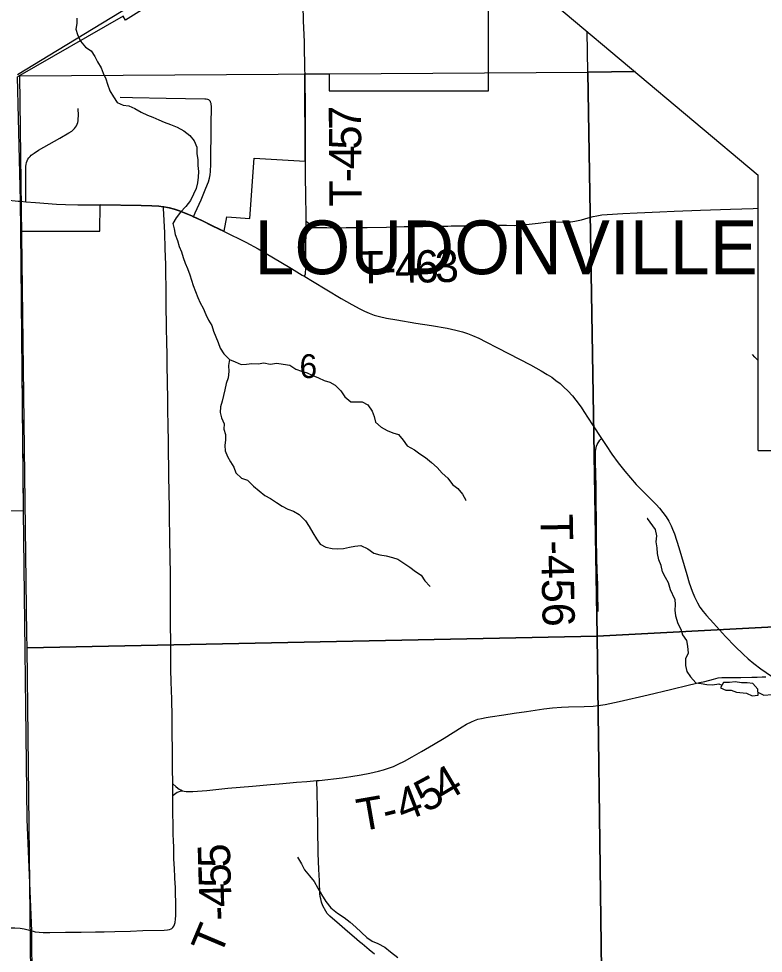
# Model space of a CAD drawing. Extents: x 0 to 34, y 0 to 22.
# Drawn here: x 4.117 to 5.429, y 15.182 to 16.828 of the extents above; entities that cross this region are included whole.
import ezdxf

# ---------------------------------------------------------------- set-up
doc = ezdxf.new("R2010")
doc.units = 0
for name, color, linetype in [('GM_X_City_Street', 7, 'Continuous'), ('GM_X_County_Road', 7, 'Continuous'), ('GM_X_County_Road_Text', 7, 'Continuous'), ('GM_X_County_Text', 7, 'Continuous'), ('GM_X_Interchange_Ramps', 7, 'Continuous'), ('GM_X_Minor_River_Text', 7, 'Continuous'), ('GM_X_State_Location', 7, 'Continuous'), ('GM_X_State_Route', 7, 'Continuous'), ('GM_X_Township_Text', 7, 'Continuous'), ('SH_Text', 7, 'Continuous')]:
    doc.layers.add(name, color=color, linetype=linetype)

msp = doc.modelspace()

# ---------------------------------------------------------------- linework, layer by layer
at = {"layer": 'GM_X_County_Road'}
msp.add_line((4.1203, 16.5064), (4.1296, 16.5056), dxfattribs=at)
for points in [[(4.0462, 16.5135), (4.0536, 16.5129), (4.0752, 16.5107), (4.0939, 16.5088), (4.1156, 16.5068), (4.1203, 16.5064)], [(4.1296, 16.5056), (4.1462, 16.5042), (4.1835, 16.5016), (4.1991, 16.501), (4.2212, 16.5004), (4.2606, 16.5), (4.3328, 16.4993), (4.3514, 16.4986), (4.3638, 16.4977), (4.3717, 16.4967)], [(4.3717, 16.4967), (4.373, 16.4965), (4.3821, 16.4948), (4.391, 16.4926), (4.3998, 16.4896), (4.4113, 16.4852), (4.4228, 16.4805), (4.425, 16.4793)], [(4.425, 16.4793), (4.4393, 16.4724), (4.459, 16.4629), (4.4789, 16.4531)], [(4.4789, 16.4531), (4.517, 16.4344), (4.5388, 16.4226), (4.563, 16.4086), (4.5975, 16.3879), (4.6162, 16.3765), (4.6208, 16.3738)], [(4.6208, 16.3738), (4.6346, 16.3655), (4.6853, 16.3352), (4.7036, 16.3244), (4.7177, 16.3168), (4.7261, 16.3128), (4.7344, 16.3091), (4.7433, 16.306), (4.7525, 16.3036), (4.7647, 16.3008), (4.783, 16.2976), (4.8167, 16.2918), (4.8441, 16.2875), (4.8717, 16.2828), (4.8868, 16.2796), (4.8987, 16.2765), (4.9075, 16.2736), (4.9162, 16.2703), (4.9275, 16.2652), (4.9402, 16.259), (4.9607, 16.2484), (5.0186, 16.2183), (5.0377, 16.2079), (5.0483, 16.2016), (5.0561, 16.1965), (5.0635, 16.191), (5.0707, 16.1852), (5.0776, 16.179), (5.0842, 16.1725), (5.0927, 16.1635), (5.0985, 16.1563), (5.1077, 16.1439), (5.1129, 16.1361), (5.128, 16.1125), (5.1435, 16.0887)], [(5.1435, 16.0887), (5.1517, 16.0761), (5.1621, 16.0607), (5.1731, 16.0457), (5.1846, 16.031), (5.1946, 16.0192), (5.2051, 16.0077), (5.2225, 15.99), (5.24, 15.9724), (5.2462, 15.9656), (5.2521, 15.9584), (5.2574, 15.9508), (5.2622, 15.9429), (5.2665, 15.9347), (5.269, 15.9291), (5.2722, 15.9204), (5.2803, 15.8964), (5.294, 15.8492), (5.2985, 15.8345), (5.3034, 15.8199), (5.3074, 15.8098), (5.3128, 15.7993), (5.3172, 15.7916), (5.3227, 15.7839), (5.3287, 15.7768), (5.3409, 15.763), (5.3623, 15.7397), (5.3792, 15.7219), (5.3931, 15.7088), (5.4023, 15.7004), (5.4119, 15.6924), (5.4243, 15.6831), (5.4432, 15.6697)]]:
    msp.add_lwpolyline(points, dxfattribs=at)
at = {"layer": 'GM_X_County_Road_Text'}
for points in [[(4.2192, 16.8292), (4.2191, 16.8197), (4.2175, 16.8095), (4.2204, 16.8), (4.226, 16.7886), (4.2347, 16.7782), (4.2448, 16.7717), (4.2512, 16.7618), (4.2557, 16.7523), (4.262, 16.7416), (4.2657, 16.7321), (4.2702, 16.7222), (4.2732, 16.7127), (4.2772, 16.7013), (4.284, 16.6902), (4.2903, 16.6807), (4.3009, 16.6756), (4.3111, 16.6744), (4.3217, 16.6698), (4.3326, 16.6636), (4.3436, 16.6582), (4.3534, 16.6547), (4.3636, 16.65), (4.3734, 16.6458), (4.3844, 16.6415), (4.3961, 16.6369), (4.4078, 16.6307), (4.4183, 16.6226), (4.4258, 16.6131), (4.4307, 16.602), (4.431, 16.5899), (4.4324, 16.58), (4.4327, 16.5694), (4.4334, 16.5592), (4.4329, 16.5489), (4.4321, 16.5387), (4.4297, 16.5289), (4.4251, 16.519), (4.4197, 16.5081), (4.4112, 16.4972), (4.4017, 16.4874), (4.3944, 16.4772), (4.3886, 16.4674), (4.3905, 16.4579), (4.3926, 16.448), (4.3967, 16.4374), (4.3997, 16.4271), (4.4038, 16.4176), (4.4067, 16.4073), (4.4104, 16.3974), (4.4141, 16.3879), (4.4186, 16.3769), (4.4212, 16.3674), (4.4241, 16.3579), (4.4282, 16.3476), (4.4323, 16.337), (4.4364, 16.3274), (4.4416, 16.3179), (4.4464, 16.3069), (4.4513, 16.297), (4.4573, 16.2874), (4.4598, 16.2775), (4.4639, 16.2676), (4.4684, 16.2577), (4.4721, 16.2479), (4.4785, 16.2376), (4.4882, 16.2276), (4.4981, 16.2237), (4.5086, 16.2191), (4.5181, 16.2194), (4.5276, 16.2208), (4.5386, 16.22), (4.5488, 16.2221), (4.5598, 16.2198), (4.5716, 16.2212), (4.5829, 16.2195), (4.5947, 16.2175), (4.6052, 16.2106), (4.6154, 16.2071), (4.6252, 16.204), (4.6351, 16.1994), (4.6449, 16.1955), (4.6551, 16.1908), (4.6649, 16.1877), (4.6747, 16.1823), (4.6845, 16.1724)], [(5.4199, 16.2257), (5.4142, 16.2321), (5.4101, 16.2363)], [(4.4882, 16.2276), (4.4866, 16.217), (4.4873, 16.2068), (4.4857, 16.1954), (4.4826, 16.1856), (4.4802, 16.1742), (4.4755, 16.1545), (4.4724, 16.1443), (4.4719, 16.1345), (4.4741, 16.125), (4.4786, 16.1147), (4.4785, 16.1052), (4.4811, 16.0957), (4.481, 16.0862), (4.4802, 16.0764), (4.4805, 16.0669), (4.4845, 16.057), (4.4902, 16.0475), (4.4961, 16.0379), (4.4995, 16.028), (4.5096, 16.0188), (4.5198, 16.015), (4.5307, 16.0046), (4.5405, 15.9962), (4.5507, 15.9881), (4.5605, 15.9831), (4.5711, 15.9758), (4.5809, 15.9693), (4.591, 15.9639), (4.6009, 15.9604), (4.6111, 15.955), (4.622, 15.9435), (4.6287, 15.9336), (4.635, 15.9222), (4.6418, 15.9119), (4.6478, 15.9023), (4.658, 15.8969), (4.6689, 15.8949), (4.6788, 15.8945), (4.689, 15.8951), (4.6996, 15.8969), (4.7091, 15.8987), (4.7198, 15.9002), (4.7318, 15.894), (4.7428, 15.8867), (4.7534, 15.8835), (4.7643, 15.8819), (4.7753, 15.8788), (4.7851, 15.876), (4.7953, 15.8688), (4.8059, 15.8622), (4.816, 15.8542), (4.8258, 15.848), (4.8322, 15.8381), (4.8412, 15.8285), (4.842, 15.8281)], [(4.6845, 16.1724), (4.6912, 16.1621), (4.7021, 16.1532), (4.7222, 16.1531), (4.732, 16.1477), (4.7399, 16.1366), (4.7429, 16.1271), (4.7454, 16.1172), (4.7556, 16.1088), (4.7658, 16.1026), (4.776, 16.0987), (4.7858, 16.0956), (4.7944, 16.0857), (4.8016, 16.0757), (4.814, 16.0688), (4.8238, 16.0615), (4.8336, 16.055), (4.8442, 16.0465), (4.8539, 16.0374), (4.863, 16.0278), (4.8727, 16.0186), (4.881, 16.0075), (4.8908, 16.0006), (4.8987, 15.9903), (4.9046, 15.98), (4.9042, 15.9796)], [(5.273, 15.8056), (5.2653, 15.822), (5.2616, 15.8342), (5.2568, 15.8437), (5.2515, 15.8536), (5.2486, 15.865), (5.2449, 15.8749), (5.2423, 15.8859), (5.2416, 15.8958), (5.2402, 15.9064), (5.2414, 15.9174), (5.2389, 15.9284), (5.2246, 15.9475), (5.2243, 15.9479)], [(5.273, 15.8056), (5.2735, 15.7958), (5.2728, 15.7859), (5.2744, 15.7761), (5.2783, 15.7628), (5.2833, 15.753), (5.2865, 15.7428), (5.2934, 15.733), (5.295, 15.7227), (5.2966, 15.7106), (5.2918, 15.7007), (5.2919, 15.689), (5.2942, 15.6784), (5.3004, 15.6685), (5.31, 15.658), (5.3194, 15.6569), (5.3293, 15.6555), (5.3395, 15.6545), (5.3505, 15.6564), (5.3559, 15.6538)], [(5.4194, 15.6418), (5.4295, 15.6362), (5.4447, 15.6375)], [(4.608, 15.3513), (4.6153, 15.3396), (4.6207, 15.329), (4.6291, 15.3181), (4.6375, 15.3083), (4.6437, 15.2966), (4.6506, 15.2852), (4.6579, 15.2728), (4.6668, 15.2619), (4.6786, 15.2525), (4.6904, 15.245), (4.7007, 15.2367), (4.711, 15.2277), (4.7301, 15.2097), (4.7397, 15.2033), (4.7499, 15.1992), (4.7621, 15.1925), (4.772, 15.1846), (4.785, 15.1741)]]:
    msp.add_lwpolyline(points, dxfattribs=at)
at = {"layer": 'GM_X_County_Text'}
msp.add_lwpolyline([(4.1146, 16.7296), (4.185, 16.7727), (4.3934, 16.8994)], dxfattribs=at)
at = {"layer": 'GM_X_Interchange_Ramps'}
for points in [[(4.6214, 16.732), (4.6214, 16.733), (4.6213, 16.7361), (4.6212, 16.741), (4.6211, 16.7443), (4.621, 16.7494), (4.6209, 16.7541), (4.621, 16.7567), (4.621, 16.7599), (4.6207, 16.7628), (4.6206, 16.7658), (4.6205, 16.7719), (4.6202, 16.7874), (4.6189, 16.8245), (4.6172, 16.8799), (4.6156, 16.9322), (4.6153, 16.9575), (4.6153, 16.9681), (4.6153, 16.9872), (4.6153, 16.9997), (4.6151, 17.0071), (4.6145, 17.0131), (4.6135, 17.018)], [(4.6219, 16.5766), (4.6219, 16.5966), (4.6219, 16.6039), (4.622, 16.6136), (4.6221, 16.6218), (4.6221, 16.631), (4.6222, 16.6446), (4.6223, 16.6553), (4.6223, 16.6618), (4.6224, 16.6676), (4.6223, 16.6738), (4.6221, 16.6845), (4.6219, 16.6936), (4.6218, 16.7018), (4.6217, 16.7105), (4.6216, 16.7171), (4.6216, 16.7207), (4.6215, 16.7265), (4.6214, 16.731), (4.6214, 16.732)], [(4.6236, 16.4712), (4.6236, 16.4721), (4.6235, 16.4812), (4.6234, 16.4904), (4.623, 16.5081), (4.6226, 16.5241), (4.6221, 16.5425), (4.6221, 16.5484), (4.622, 16.5579), (4.6219, 16.5766)], [(4.384, 15.8716), (4.3839, 15.8798), (4.3833, 15.9109), (4.3825, 15.9544), (4.3823, 15.973), (4.3821, 15.9864), (4.3819, 16), (4.3816, 16.0168), (4.3813, 16.0351), (4.3808, 16.0662), (4.3805, 16.0817), (4.3801, 16.1125), (4.3798, 16.1373), (4.3797, 16.159), (4.3793, 16.1869), (4.3787, 16.219), (4.3784, 16.2366), (4.3781, 16.2584), (4.3775, 16.2832), (4.3773, 16.2925), (4.3768, 16.3173), (4.3764, 16.3329), (4.3766, 16.3577), (4.3763, 16.3764), (4.376, 16.395), (4.3751, 16.4229), (4.3742, 16.4509), (4.3732, 16.4726), (4.3719, 16.4941), (4.3717, 16.4967)], [(4.8092, 16.462), (4.8292, 16.4623), (4.8611, 16.4625), (4.8672, 16.4627), (4.8732, 16.4629), (4.8789, 16.4632), (4.8918, 16.4633), (4.9125, 16.4634), (4.927, 16.4637), (4.9504, 16.4641), (4.9621, 16.4642), (4.9761, 16.4641), (4.9906, 16.464), (5.0007, 16.4647), (5.0102, 16.4657), (5.0164, 16.4663), (5.032, 16.4681), (5.0456, 16.4695), (5.0613, 16.4703), (5.0775, 16.4697), (5.0842, 16.4701), (5.0899, 16.4704), (5.0967, 16.4717), (5.1027, 16.4727), (5.1084, 16.4739), (5.1203, 16.4772), (5.1293, 16.4797), (5.1353, 16.4811), (5.1445, 16.4826), (5.1538, 16.4834), (5.1816, 16.4848), (5.2065, 16.4859), (5.2468, 16.4877), (5.2716, 16.4889), (5.3181, 16.4907), (5.3709, 16.4925), (5.4112, 16.494), (5.4199, 16.4946)], [(4.6234, 16.4558), (4.6235, 16.4614), (4.6236, 16.4712)], [(4.6236, 16.4712), (4.6295, 16.4665), (4.633, 16.4637), (4.6373, 16.4603)], [(4.6208, 16.3738), (4.6213, 16.3757), (4.6219, 16.3785), (4.6223, 16.3816), (4.6226, 16.3864), (4.6227, 16.3895), (4.6226, 16.3957), (4.6227, 16.4112), (4.6227, 16.4159), (4.6227, 16.4214), (4.6227, 16.4261), (4.6229, 16.4336), (4.6232, 16.4454), (4.6234, 16.4513), (4.6234, 16.4558)], [(4.6234, 16.4558), (4.6277, 16.4577), (4.6313, 16.459), (4.6336, 16.4597), (4.6349, 16.46), (4.6363, 16.4601), (4.6373, 16.4603)], [(4.6373, 16.4603), (4.6379, 16.4603), (4.6441, 16.4604), (4.6596, 16.46), (4.6752, 16.4599), (4.6938, 16.46), (4.7167, 16.4603), (4.7311, 16.4605), (4.7652, 16.4609), (4.7963, 16.4618), (4.8092, 16.462)], [(5.1381, 15.7837), (5.1381, 15.7899), (5.1375, 15.8117), (5.1373, 15.821), (5.1372, 15.8303), (5.1371, 15.8334), (5.1369, 15.8427), (5.1363, 15.8581), (5.136, 15.8642), (5.1357, 15.8704), (5.1354, 15.8828), (5.1352, 15.9076), (5.1349, 15.9356), (5.1343, 15.9853), (5.1341, 16.004), (5.1339, 16.0258), (5.1337, 16.032), (5.1334, 16.0413), (5.1332, 16.0506), (5.1331, 16.0599), (5.1332, 16.0661), (5.1336, 16.0692), (5.1342, 16.0723), (5.135, 16.0753), (5.1362, 16.0781), (5.1377, 16.0808), (5.139, 16.0826), (5.1411, 16.0855), (5.1435, 16.0887)], [(4.3874, 15.5639), (4.387, 15.5981), (4.3866, 15.6292), (4.3856, 15.6602), (4.3851, 15.6819), (4.3847, 15.7037), (4.3847, 15.7099), (4.3847, 15.7266), (4.3847, 15.7395), (4.3846, 15.7517), (4.3846, 15.7649), (4.3845, 15.7782), (4.3844, 15.7925), (4.3843, 15.8116), (4.3842, 15.8364), (4.3841, 15.8581), (4.384, 15.8716)], [(4.642, 15.486), (4.6464, 15.4864), (4.6865, 15.4909), (4.7019, 15.4932), (4.7203, 15.4962), (4.7355, 15.4991), (4.7506, 15.5024), (4.7596, 15.5048), (4.7685, 15.5076), (4.7772, 15.5109), (4.7857, 15.5147), (4.7968, 15.5203), (4.8104, 15.5278), (4.8266, 15.537), (4.848, 15.5496), (4.8666, 15.5609), (4.898, 15.5808), (4.9061, 15.5855), (4.9145, 15.5897), (4.9202, 15.5921), (4.9261, 15.594), (4.9321, 15.5956), (4.9404, 15.5972), (4.9473, 15.5983), (4.9717, 15.6021), (4.9901, 15.6047), (5.0116, 15.6077), (5.0422, 15.6122), (5.0576, 15.614), (5.0731, 15.6153), (5.0854, 15.6158), (5.1134, 15.6164), (5.1289, 15.6173), (5.1381, 15.6182), (5.1504, 15.6201), (5.1747, 15.6251), (5.2261, 15.6372), (5.2654, 15.6463), (5.2986, 15.6544), (5.3167, 15.6589), (5.3257, 15.6608), (5.3413, 15.6648), (5.3495, 15.667), (5.3559, 15.6677), (5.3634, 15.6677), (5.3736, 15.6675), (5.3893, 15.6675), (5.4087, 15.6679), (5.418, 15.6683), (5.4271, 15.6685), (5.4332, 15.6688)], [(4.3884, 15.4801), (4.3882, 15.4865), (4.388, 15.5024), (4.3877, 15.5205), (4.3877, 15.536), (4.3876, 15.5484), (4.3875, 15.5608), (4.3874, 15.5639)], [(4.3884, 15.4801), (4.3939, 15.4755), (4.3972, 15.4728), (4.3997, 15.4711), (4.4025, 15.4696), (4.4056, 15.4682)], [(4.3884, 15.4595), (4.3884, 15.4671), (4.3885, 15.4772), (4.3884, 15.4801)], [(4.4056, 15.4682), (4.4085, 15.4674), (4.4121, 15.4669), (4.4176, 15.4666), (4.4238, 15.4667), (4.4486, 15.4687), (4.464, 15.4703), (4.4856, 15.4724), (4.5072, 15.4743), (4.5288, 15.4763), (4.5603, 15.4792), (4.576, 15.4805), (4.5943, 15.482), (4.6062, 15.483), (4.6248, 15.4843), (4.642, 15.486)], [(4.7437, 15.1804), (4.7343, 15.1878), (4.7218, 15.1985), (4.7171, 15.2021), (4.7077, 15.2101), (4.696, 15.2204), (4.6822, 15.2322), (4.6649, 15.2469), (4.6604, 15.252), (4.6578, 15.256), (4.6528, 15.2655), (4.6506, 15.2717), (4.6495, 15.2747), (4.649, 15.2774), (4.6481, 15.2817), (4.6477, 15.2868), (4.6473, 15.2961), (4.647, 15.2992), (4.6466, 15.3097), (4.6461, 15.3195), (4.6456, 15.3299), (4.6447, 15.3578), (4.644, 15.4013), (4.6433, 15.4417), (4.643, 15.4603), (4.6425, 15.4727), (4.6422, 15.479), (4.642, 15.486)], [(4.3884, 15.4595), (4.3911, 15.462), (4.3935, 15.4639), (4.396, 15.4654), (4.3983, 15.4664), (4.4015, 15.4674), (4.4056, 15.4682)], [(4.3891, 15.4033), (4.3889, 15.4122), (4.3887, 15.425), (4.3885, 15.4325), (4.3884, 15.4424), (4.3884, 15.4503), (4.3884, 15.4595)], [(4.1402, 15.2211), (4.1421, 15.2205), (4.1459, 15.2198), (4.1527, 15.2191), (4.16, 15.2186), (4.1719, 15.2185), (4.1992, 15.2187), (4.2271, 15.2191), (4.2519, 15.2194), (4.2674, 15.2196), (4.286, 15.2201), (4.314, 15.221), (4.3357, 15.2218), (4.373, 15.2227), (4.3792, 15.2232), (4.3824, 15.2238), (4.3855, 15.2249), (4.3868, 15.2257), (4.3882, 15.2269), (4.3902, 15.2296), (4.3916, 15.2326), (4.3924, 15.2357), (4.3934, 15.2419), (4.3938, 15.2482), (4.3938, 15.2606), (4.393, 15.2978), (4.3922, 15.3133), (4.3919, 15.3164), (4.3912, 15.3308), (4.3904, 15.348), (4.3901, 15.3581), (4.3899, 15.3679), (4.3896, 15.3804), (4.3893, 15.3908), (4.3891, 15.3993), (4.3891, 15.4033)], [(3.882, 15.2231), (3.8894, 15.2232), (3.9019, 15.2234), (3.9174, 15.2236), (3.936, 15.2238), (3.9547, 15.2239), (3.9733, 15.2241), (3.9982, 15.2243), (4.02, 15.2246), (4.0449, 15.2252), (4.0604, 15.2255), (4.0822, 15.2263), (4.1009, 15.2268), (4.1102, 15.2267), (4.1195, 15.2259), (4.1266, 15.2248), (4.1333, 15.2232), (4.1402, 15.2211)]]:
    msp.add_lwpolyline(points, dxfattribs=at)
at = {"layer": 'GM_X_Minor_River_Text'}
for points in [[(5.4104, 15.6569), (5.4005, 15.658), (5.3907, 15.6583), (5.3793, 15.6597), (5.3691, 15.6589), (5.3588, 15.6588), (5.3532, 15.6493), (5.3627, 15.6455), (5.3722, 15.6452), (5.3817, 15.6419)], [(5.3817, 15.6419), (5.3995, 15.6402), (5.4091, 15.6353), (5.4197, 15.6365), (5.4192, 15.6471), (5.4104, 15.6569)]]:
    msp.add_lwpolyline(points, dxfattribs=at)
at = {"layer": 'GM_X_State_Route'}
for points in [[(4.6133, 17.0186), (4.3049, 16.8256), (4.3011, 16.8324), (4.1149, 16.7255)], [(3.4757, 15.9666), (4.1252, 15.961), (4.1206, 16.454), (4.26, 16.454), (4.2604, 16.5006), (4.3326, 16.4999), (4.3512, 16.4992), (4.3635, 16.4982), (4.3715, 16.4972), (4.3727, 16.497), (4.3818, 16.4954), (4.3908, 16.4931), (4.3996, 16.4901), (4.4111, 16.4857), (4.4226, 16.4811), (4.4248, 16.4799), (4.4391, 16.473), (4.4588, 16.4635), (4.4787, 16.4536), (4.4836, 16.479), (4.5243, 16.4762), (4.5318, 16.5825), (4.6217, 16.5772), (4.6212, 16.7315), (4.6641, 16.7311), (4.6641, 16.7008), (4.9445, 16.7008), (4.9445, 16.966)], [(5.2028, 16.735), (5.1198, 16.7337), (5.1185, 16.8058)], [(6.1232, 16.0674), (6.1276, 15.7926), (5.1364, 15.7406), (5.1198, 16.7337), (5.2028, 16.735)], [(1.8602, 14.3866), (4.1451, 14.3866), (4.14, 15.2216), (4.132, 15.4174), (4.1252, 15.9611), (4.1251, 15.9712), (4.1206, 16.454), (4.1201, 16.507), (4.1149, 16.7255)], [(4.2954, 16.6897), (4.3173, 16.6894), (4.3768, 16.6884), (4.4448, 16.6872), (4.4474, 16.687), (4.4497, 16.6865), (4.4511, 16.6859), (4.4521, 16.6851), (4.4531, 16.6841), (4.4538, 16.6832)], [(4.425, 16.4793), (4.428, 16.4864), (4.4381, 16.5093), (4.4467, 16.5294), (4.4512, 16.541), (4.4531, 16.5469), (4.4543, 16.553), (4.4549, 16.5591), (4.4553, 16.5716), (4.4559, 16.6404), (4.4563, 16.6742), (4.4561, 16.6767), (4.4559, 16.6778), (4.4557, 16.679), (4.4554, 16.6801), (4.455, 16.6811), (4.4545, 16.6822), (4.4538, 16.6832)], [(4.1296, 16.5056), (4.1296, 16.5133), (4.1296, 16.5224), (4.1294, 16.5378), (4.1292, 16.5593), (4.1295, 16.5685), (4.1298, 16.5714), (4.1306, 16.575), (4.1317, 16.5779), (4.133, 16.5807), (4.1348, 16.5832), (4.1368, 16.5855), (4.139, 16.5877), (4.1439, 16.5915), (4.1517, 16.5963), (4.1704, 16.6071), (4.1893, 16.6176), (4.2054, 16.6268), (4.2105, 16.6302), (4.2129, 16.6322), (4.2151, 16.6344), (4.217, 16.6368), (4.2186, 16.6394), (4.2199, 16.6422), (4.2209, 16.6451), (4.2215, 16.6481), (4.2219, 16.6512), (4.2221, 16.6573), (4.2218, 16.6697)]]:
    msp.add_lwpolyline(points, dxfattribs=at)
for points in [[(4.119, 16.7272), (5.1198, 16.7337), (5.1364, 15.7406), (4.1315, 15.7198), (4.1312, 15.7435)], [(5.1364, 15.7406), (6.1276, 15.7926), (6.1462, 14.7998), (5.7574, 14.7844), (5.149, 14.7448)], [(4.1315, 15.7198), (5.1364, 15.7406), (5.149, 14.7448), (4.1433, 14.7233), (4.1432, 14.7291)]]:
    msp.add_lwpolyline(points, close=True, dxfattribs=at)
at = {"layer": 'SH_Text'}
for q in [(5.4199, 16.5526), (7.5483, 16.0674)]:
    msp.add_line((5.4199, 16.0674), q, dxfattribs=at)
msp.add_lwpolyline([(5.4199, 16.8504), (4.7398, 17.1239), (5.4199, 16.5526)], dxfattribs=at)

# ---------------------------------------------------------------- texts
at = {"layer": 'GM_X_City_Street'}
msp.add_text('LOUDONVILLE', height=0.094697, rotation=0, dxfattribs=at).set_placement((4.5322, 16.378))
at = {"layer": 'GM_X_State_Location'}
msp.add_text('6', height=0.0419, rotation=0, dxfattribs=at).set_placement((4.6116, 16.1951))
at = {"layer": 'GM_X_Township_Text'}
for s, height, rotation, p in [('7', 0.0568, 90.3861, (4.7202, 16.6325)), ('5', 0.0568, 90.3218, (4.7204, 16.5978)), ('4', 0.0568, 90.3049, (4.7206, 16.563)), ('-', 0.0568, 90.2987, (4.7207, 16.5399)), ('T', 0.0568, 90.2973, (4.721, 16.4975)), ('T', 0.0568, 0.8829, (4.7144, 16.3615)), ('4', 0.0568, 0.9182, (4.7803, 16.3625)), ('6', 0.0568, 1.0227, (4.8154, 16.3631)), ('3', 0.0568, 1.4372, (4.8508, 16.3637)), ('-', 0.0568, 0.8821, (4.7569, 16.3621)), ('T-456', 0.05682, 271.1137, (5.0363, 15.955)), ('4', 0.0568, 30.7421, (4.8671, 15.4465)), ('5', 0.0568, 28.3152, (4.834, 15.4286)), ('4', 0.0568, 21.0862, (4.7942, 15.4127)), ('T', 0.0568, 9.8717, (4.7181, 15.3964)), ('-', 0.0568, 14.3375, (4.7647, 15.4047)), ('5', 0.0568, 91.6186, (4.49, 15.3336)), ('5', 0.0568, 91.7186, (4.491, 15.2986)), ('4', 0.0568, 91.5302, (4.492, 15.2635)), ('-', 0.0568, 92.4197, (4.4929, 15.2404)), ('T', 0.0568, 67.1537, (4.4716, 15.1745))]:
    msp.add_text(s, height=height, rotation=rotation, dxfattribs=at).set_placement(p)

doc.saveas('drawing.dxf')
